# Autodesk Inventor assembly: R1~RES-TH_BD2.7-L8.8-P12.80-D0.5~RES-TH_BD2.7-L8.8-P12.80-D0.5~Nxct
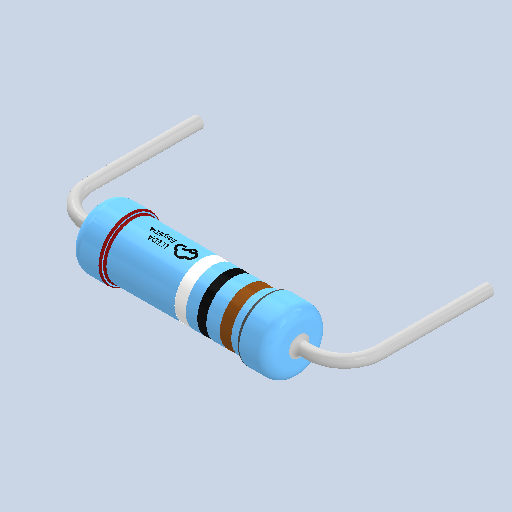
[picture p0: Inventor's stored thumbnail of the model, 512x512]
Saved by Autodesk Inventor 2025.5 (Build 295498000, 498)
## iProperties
Created: 2026-10
Part Number: R1~RES-TH_BD2.7-L8.8-P12.80-D0.5~RES-TH_BD2.7-L8.8-P12.80-D0.5~Nxct
Document SubType Name: Assembly
Designer: Luis M
Author: Luis M
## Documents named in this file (2)
- C:\Users\Luis M\Downloads\3D_PCB1_2026-10-28\R1~RES-TH_BD2.7-L8.8-P12.80-D0.5~RES-TH_BD2.7-L8.8-P12.80-D0.5~Nxct.iam
- C:\Users\Luis M\Downloads\3D_PCB1_2026-10-28\RES-TH_BD2.7-L8.8-P12.80-D0.5~RES-TH_BD2.7-L8.8-P12.80-D0.5~UAzC.ipt
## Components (1 placed, 1 different names)
1. R1->0
